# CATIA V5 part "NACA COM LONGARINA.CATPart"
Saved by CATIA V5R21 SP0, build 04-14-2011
Part number: Part4
Bounding box of the stored display mesh (mm): x 0 to 350, y 0 to 200, z -8.46 to 15.76
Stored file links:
  C:\Users\rodri\OneDrive\Área de Trabalho\FACULDADE\3°semestre\Sistemas Aeroespaciais\Projeto de avião 2019-02\CAD\NACA COM LONGARINA.CATPart
  C:\Users\rodri\OneDrive\Área de Trabalho\FACULDADE\3°semestre\Sistemas Aeroespaciais\Projeto de avião 2019-02\CAD\Naca 2412-Longarina.CATPart
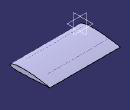
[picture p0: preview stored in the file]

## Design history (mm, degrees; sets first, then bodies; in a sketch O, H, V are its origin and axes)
Body1 (main body)
  Sketch1 on yz-plane, origin (0, 0, 0), H (0, 1, 0), V (0, 0, 1)
    point P1 (200, 0)
    unspec C1
    unspec C2
    point P3 (20, 2)
    circle A1 centre (20, 2) radius 5
    point P4 (50, 3)
    circle A2 centre (50, 3) radius 7.5
    point P5 (75, 4)
    circle A3 centre (75, 4) radius 7.5
    point P6 (100, 4)
    circle A4 centre (100, 4) radius 7.5
    point P7 (125, 3)
    circle A5 centre (125, 3) radius 5
    line L1 (30, 11) -> (36, 11)
    line L2 (36, 11) -> (36, -6)
    line L3 (36, -6) -> (30, -6)
    line L4 (30, -6) -> (30, 11)
    line L5 (140, 8) -> (144, 8)
    line L6 (144, 8) -> (144, -2)
    line L7 (144, -2) -> (140, -2)
    line L8 (140, -2) -> (140, 8)
    distance V P3 = 20
    distance V P4 = 50
    distance V P5 = 75
    distance V P6 = 100
    distance V P7 = 125
    distance H P3 = 2
    distance H P4 = 3
    distance P5 H = 4
    distance P6 H = 4
    distance P7 H = 3
    radius A1 = 5
    radius A2 = 7.5
    radius A3 = 7.5
    radius A4 = 7.5
    radius A5 = 5
    distance H L3 = 6
    length L1 = 6
    length L2 = 17
    distance V L4 = 30
    length L8 = 10
    distance V L8 = 140
    length L7 = 4
    distance H L7 = 2
    distance P1 V = 200
    horizontal: L1 H, L3 H, L5 H, L7 H
    vertical: L2 V, L4 V, L6 V, L8 V
  Pad1: profile Sketch1, direction (1, 0, 0), length 300
  Sketch2 on end face of Pad1, origin (300, 0, 0), H (0, 1, 0), V (0, 0, 1)
    projected curve E1 from edge [face of Pad1 from Sketch1.C2 | end face of Pad1]
    projected curve E2 from edge [face of Pad1 from Sketch1.C1 | end face of Pad1]
  Pad2: profile Sketch2, direction (1, 0, 0), length 50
